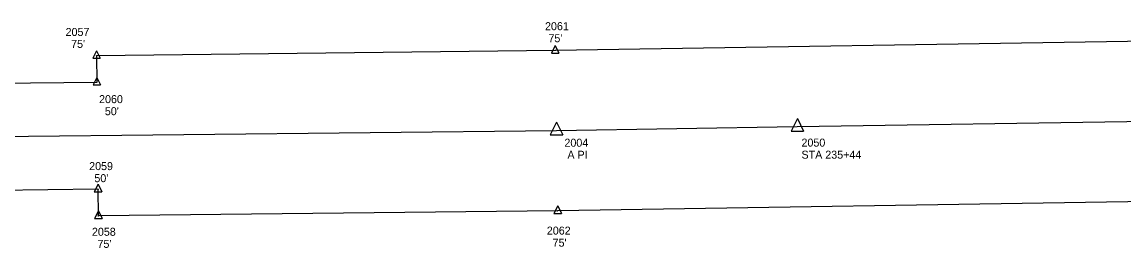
# Model space of a CAD drawing. Extents: x 1799493 to 1803621, y 522869 to 525846.
# Drawn here: x 1801530 to 1802563, y 522869 to 523081 of the extents above; entities that cross this region are included whole.
import ezdxf

# ---------------------------------------------------------------- set-up
doc = ezdxf.new("R2010")
doc.units = 0
for name, color, linetype in [('S_CAL_CORNER', 7, 'Continuous'), ('S_CAL_CORNER_ANNOT', 7, 'Continuous'), ('S_EXIST_ROW', 7, 'Continuous'), ('S_EXIST_ROW_ANNOT', 7, 'Continuous'), ('S_EXISTING_ALIGNMENT', 7, 'Continuous')]:
    doc.layers.add(name, color=color, linetype=linetype)

msp = doc.modelspace()

# ---------------------------------------------------------------- linework, layer by layer
at = {"layer": 'S_CAL_CORNER'}
for p, q in [((1802031.4, 522986.8), (1802025.5, 522975)), ((1802031.4, 522986.8), (1802025.5, 522975)), ((1802031.4, 522986.8), (1802025.5, 522975)), ((1802031.4, 522986.8), (1802037.2, 522975)), ((1802031.4, 522986.8), (1802037.2, 522975)), ((1802031.4, 522986.8), (1802037.2, 522975)), ((1802257.1, 522990.4), (1802251.2, 522978.6)), ((1802257.1, 522990.4), (1802251.2, 522978.6)), ((1802257.1, 522990.4), (1802262.9, 522978.6)), ((1802257.1, 522990.4), (1802262.9, 522978.6)), ((1802025.5, 522975), (1802037.2, 522975)), ((1802025.5, 522975), (1802037.2, 522975)), ((1802025.5, 522975), (1802037.2, 522975)), ((1802251.2, 522978.6), (1802262.9, 522978.6)), ((1802251.2, 522978.6), (1802262.9, 522978.6))]:
    msp.add_line(p, q, dxfattribs=at)
at = {"layer": 'S_EXIST_ROW'}
for p, q in [((1802599.8, 523062.9), (1802030.1, 523053.9)), ((1802030.1, 523053.9), (1801600.2, 523049.1)), ((1801600.2, 523049.1), (1801600.5, 523024.1)), ((1801600.5, 523024.1), (1800364.7, 523010.3)), ((1801601.6, 522924.1), (1800365.9, 522910.3)), ((1801601.9, 522899.1), (1801601.6, 522924.1)), ((1802602.2, 522912.9), (1802032.5, 522903.9)), ((1802032.5, 522903.9), (1801601.9, 522899.1))]:
    msp.add_line(p, q, dxfattribs=at)
at = {"layer": 'S_EXIST_ROW_ANNOT'}
for p, q in [((1802030.1, 523058.6), (1802026.6, 523051.5)), ((1802030.1, 523058.6), (1802033.6, 523051.5)), ((1801600.2, 523053.8), (1801596.7, 523046.7)), ((1801596.7, 523046.7), (1801603.7, 523046.7)), ((1801600.2, 523053.8), (1801603.7, 523046.7)), ((1801600.2, 523049.1), (1801600.2, 523049.1)), ((1802026.6, 523051.5), (1802033.6, 523051.5)), ((1802030.1, 523053.9), (1802030.1, 523053.9)), ((1801600.5, 523028.8), (1801597, 523021.7)), ((1801600.5, 523028.8), (1801604, 523021.7)), ((1801597, 523021.7), (1801604, 523021.7)), ((1801600.5, 523024.1), (1801600.5, 523024.1)), ((1801601.6, 522928.8), (1801598.1, 522921.7)), ((1801601.6, 522928.8), (1801605.1, 522921.7)), ((1801601.6, 522924.1), (1801601.6, 522924.1)), ((1801598.1, 522921.7), (1801605.1, 522921.7)), ((1801601.9, 522903.8), (1801598.4, 522896.7)), ((1801601.9, 522903.8), (1801605.4, 522896.7)), ((1802032.5, 522908.6), (1802029, 522901.5)), ((1802032.5, 522908.6), (1802036, 522901.5)), ((1802032.5, 522903.9), (1802032.5, 522903.9)), ((1801598.4, 522896.7), (1801605.4, 522896.7)), ((1801601.9, 522899.1), (1801601.9, 522899.1)), ((1802029, 522901.5), (1802036, 522901.5))]:
    msp.add_line(p, q, dxfattribs=at)
for centre, radius in [((1801600.2, 523049.1), 0.12), ((1801600.2, 523049.1), 0.06), ((1802030.1, 523053.9), 0.12), ((1802030.1, 523053.9), 0.06), ((1801600.5, 523024.1), 0.12), ((1801600.5, 523024.1), 0.06), ((1801601.6, 522924.1), 0.12), ((1801601.6, 522924.1), 0.06), ((1802032.5, 522903.9), 0.12), ((1802032.5, 522903.9), 0.06), ((1801601.9, 522899.1), 0.12), ((1801601.9, 522899.1), 0.06)]:
    msp.add_circle(centre, radius, dxfattribs=at)
at = {"layer": 'S_EXISTING_ALIGNMENT'}
for p, q in [((1803565, 523003.2), (1802257, 522982.4)), ((1802031.3, 522978.9), (1800365.3, 522960.3)), ((1802257, 522982.4), (1802031.3, 522978.9))]:
    msp.add_line(p, q, dxfattribs=at)

# ---------------------------------------------------------------- texts
at = {"layer": 'S_CAL_CORNER_ANNOT'}
for s, p in [('2004', (1802038.8, 522963.9)), ('2050', (1802261, 522964)), (' A PI', (1802038.8, 522952.6)), ('STA 235+44', (1802261, 522952.7))]:
    msp.add_text(s, height=7.5, dxfattribs=at).set_placement(p)
at = {"layer": 'S_EXIST_ROW_ANNOT'}
for s, p in [('2061', (1802020.6, 523073)), ('2057', (1801571.2, 523067.6)), ("75'", (1802023.8, 523061.7)), ("75'", (1801576.4, 523056.4)), ('2060', (1801602.6, 523004.7)), ("50'", (1801608, 522993.4)), ('2059', (1801593.3, 522942)), ("50'", (1801598.2, 522930.7)), ('2058', (1801595.9, 522880.5)), ('2062', (1802022.3, 522881.6)), ("75'", (1801601.1, 522869.2)), ("75'", (1802027.7, 522870.3))]:
    msp.add_text(s, height=7.5, dxfattribs=at).set_placement(p)

doc.saveas('drawing.dxf')
